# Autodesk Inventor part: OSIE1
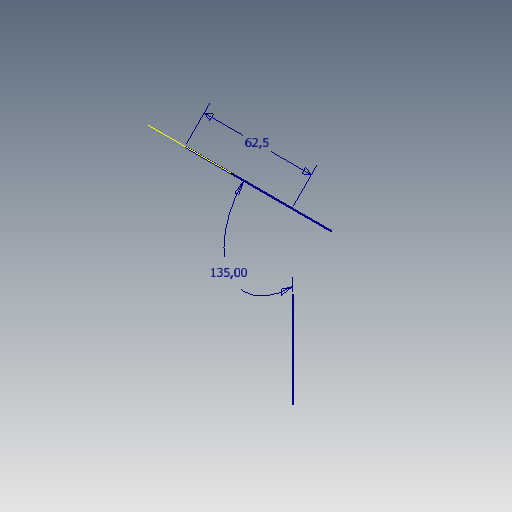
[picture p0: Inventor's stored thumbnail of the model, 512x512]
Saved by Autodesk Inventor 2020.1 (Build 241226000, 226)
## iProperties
Created: 2005-12
Part Number: OSIE1
Document SubType Name: Modeling
Designer: F.Stasiak
Density: 1 g/cm^3
Material: Ogólny
Appearance: Domyślna
Manager: www.cadconsulting.pl
Company: Fabian Stasiak CAD Consulting
Author: F.Stasiak
Subject: Zbiór ćwiczeń. Autodesk Inventor 2020. Kurs podstawowy
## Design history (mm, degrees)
sketch "Szkic1"
  geometry: L1 (16, 55.098)-(-12, 55.098) reference; L2 (0, -14.8)-(0, 24.4) reference
  constraints: 4 end point, 1 horizontal, 1 vertical, 4 other
sketch "Szkic2"
  geometry: L1 (-14.8, 0)-(24.4, 0) reference; L2 (55.098, 0)-(99.292, 44.194)
  constraints: 2 end point
  dimensions: "d0" = 62.5 distance of L2.start L2.end; "d1" = 135 deg angle of L1 L2
node "Oś konstrukcyjna1"
node "Korpusy bryłowe"
node "Korpusy powierzchniowe"
